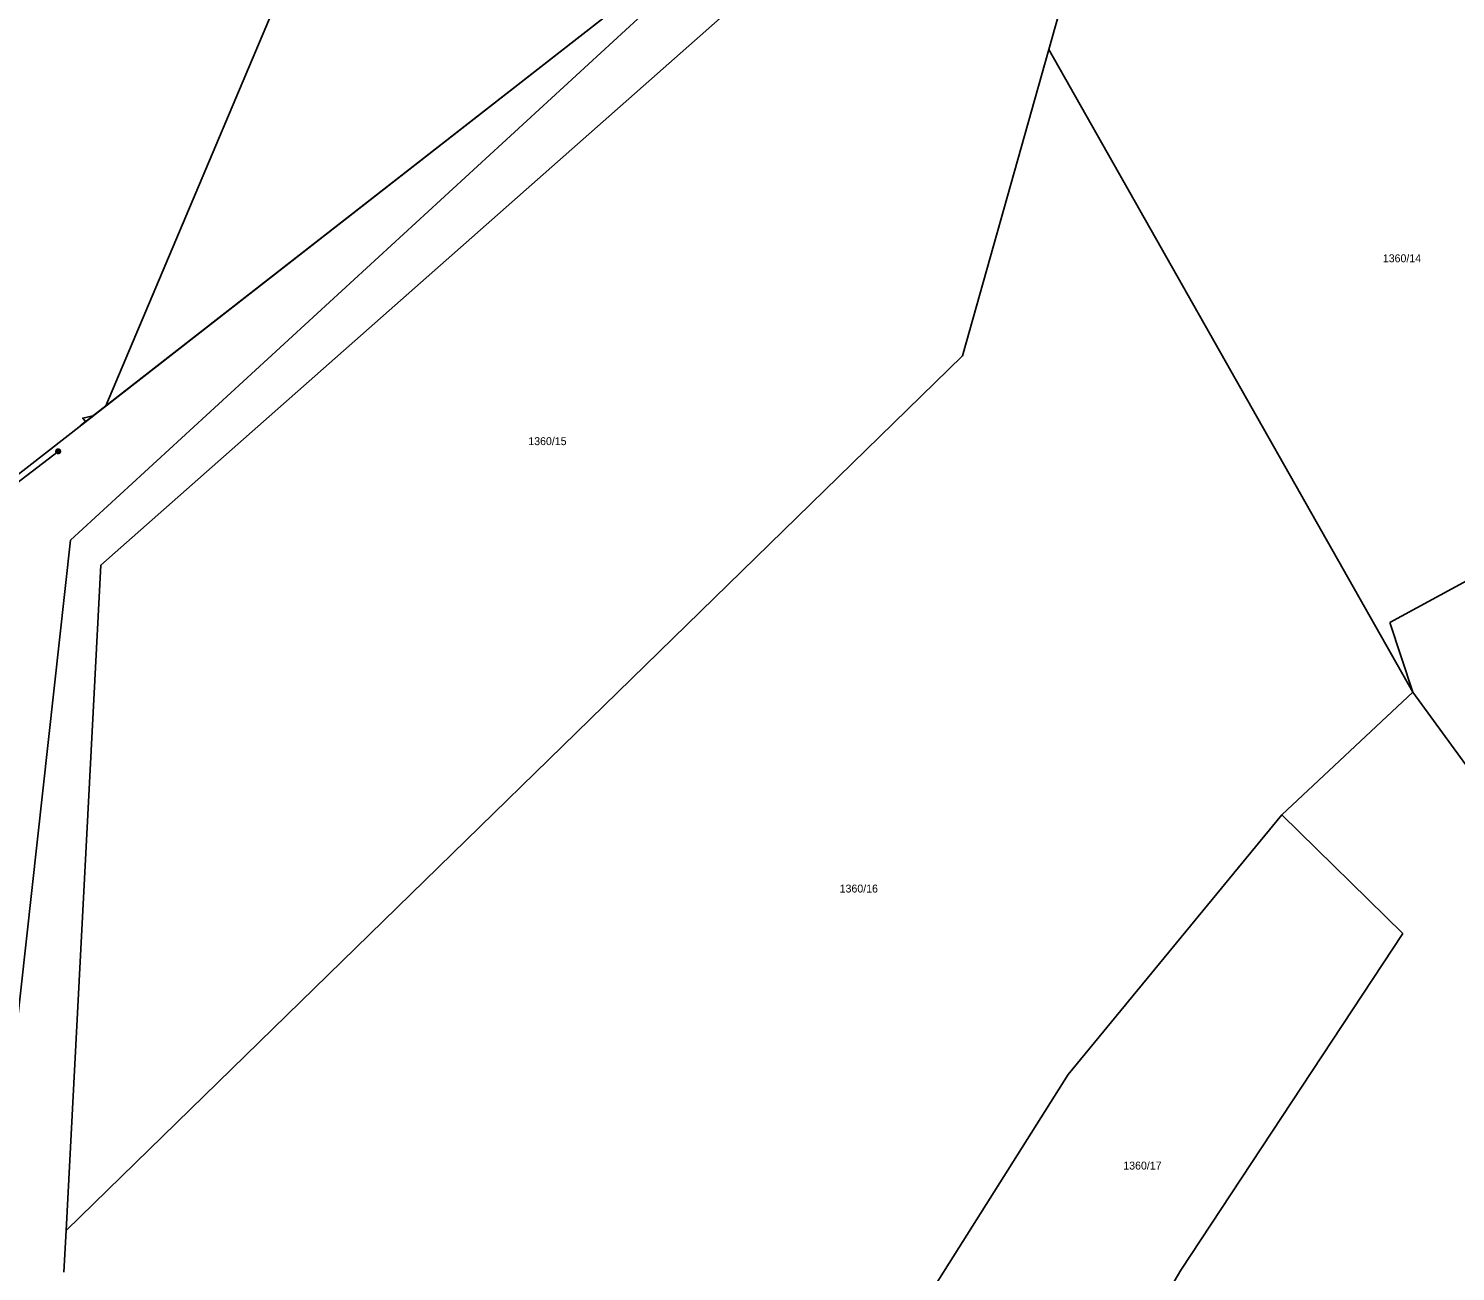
# Model space of a CAD drawing. Extents: x -747792 to -745414, y -1093712 to -1091463.
# Drawn here: x -746034.4 to -745881.2, y -1091874.7 to -1091741.3 of the extents above; entities that cross this region are included whole.
import ezdxf

# ---------------------------------------------------------------- set-up
doc = ezdxf.new("R2010")
doc.units = 0
for name, color, linetype in [('Pracovní_bod JDTM STC_VC', 7, 'Continuous'), ('Pracovní_bod NN - výška', 7, 'Continuous'), ('Pracovní_bod polohopisu - číslo', 7, 'Continuous')]:
    doc.layers.add(name, color=color, linetype=linetype)

msp = doc.modelspace()

# ---------------------------------------------------------------- linework, layer by layer
at = {"layer": 'Pracovní_bod NN - výška'}
for points in [[(-745924.91, -1091743.52), (-745913.66, -1091703.59)], [(-746026.69, -1091798.86), (-745953.12, -1091733.88)], [(-746029.94, -1091796.18), (-745967.69, -1091739)], [(-745934.16, -1091776.38), (-745924.91, -1091743.52)], [(-745924.91, -1091743.52), (-745885.81, -1091812.51)], [(-746030.4, -1091870.28), (-745934.16, -1091776.38)], [(-746038.28, -1091871.42), (-746029.94, -1091796.18)], [(-745888.29, -1091805.01), (-745872.94, -1091796.67)], [(-746030.4, -1091870.28), (-746026.69, -1091798.86)], [(-745885.81, -1091812.51), (-745888.29, -1091805.01)], [(-745885.81, -1091812.51), (-745899.88, -1091825.68)], [(-745885.81, -1091812.51), (-745827.14, -1091892.93)], [(-745922.83, -1091853.53), (-745899.88, -1091825.68)], [(-745899.88, -1091825.68), (-745886.88, -1091838.4)], [(-745886.88, -1091838.4), (-745910.73, -1091874.54)], [(-745949.4, -1091895.7), (-745922.83, -1091853.53)], [(-746030.66, -1091874.78), (-746030.4, -1091870.28)], [(-745910.73, -1091874.54), (-745928.7, -1091905.13)]]:
    msp.add_lwpolyline(points, dxfattribs=at)
at = {"layer": 'Pracovní_bod polohopisu - číslo'}
for points in [[(-746026.14, -1091781.77), (-745984.67, -1091683.58), (-746006.09, -1091734.29)], [(-746095.38, -1091835.77), (-745959.66, -1091729.93), (-746028.9, -1091783.92)], [(-746028.7, -1091783.77), (-746028.31, -1091783.46), (-746028.62, -1091783.07), (-746027.52, -1091782.85), (-746026.34, -1091781.93)], [(-746162.28, -1091887.01), (-746031.26, -1091786.65), (-746098.16, -1091837.89)], [(-746031.33, -1091786.41), (-746031.18, -1091786.41), (-746031.05, -1091786.5), (-746031.01, -1091786.65), (-746031.05, -1091786.79), (-746031.18, -1091786.88), (-746031.33, -1091786.88), (-746031.46, -1091786.79), (-746031.51, -1091786.65), (-746031.46, -1091786.5), (-746031.33, -1091786.41), (-746031.32, -1091786.43), (-746031.2, -1091786.43), (-746031.12, -1091786.47), (-746031.4, -1091786.47), (-746031.44, -1091786.51), (-746031.08, -1091786.51), (-746031.08, -1091786.55), (-746031.44, -1091786.55), (-746031.46, -1091786.59), (-746031.06, -1091786.59), (-746031.04, -1091786.63), (-746031.48, -1091786.63), (-746031.48, -1091786.67), (-746031.04, -1091786.67), (-746031.05, -1091786.71), (-746031.46, -1091786.71), (-746031.46, -1091786.75), (-746031.05, -1091786.75), (-746031.08, -1091786.79), (-746031.44, -1091786.79), (-746031.4, -1091786.83), (-746031.11, -1091786.83), (-746031.17, -1091786.87), (-746031.34, -1091786.87)]]:
    msp.add_lwpolyline(points, dxfattribs=at)

# ---------------------------------------------------------------- texts
at = {"layer": 'Pracovní_bod JDTM STC_VC'}
for s, p in [('1360/14', (-745889.04, -1091766.35)), ('1360/15', (-745980.78, -1091785.98)), ('1360/16', (-745947.35, -1091834.01)), ('1360/17', (-745916.9, -1091863.75))]:
    msp.add_text(s, height=0.85, dxfattribs=at).set_placement(p)

doc.saveas('drawing.dxf')
